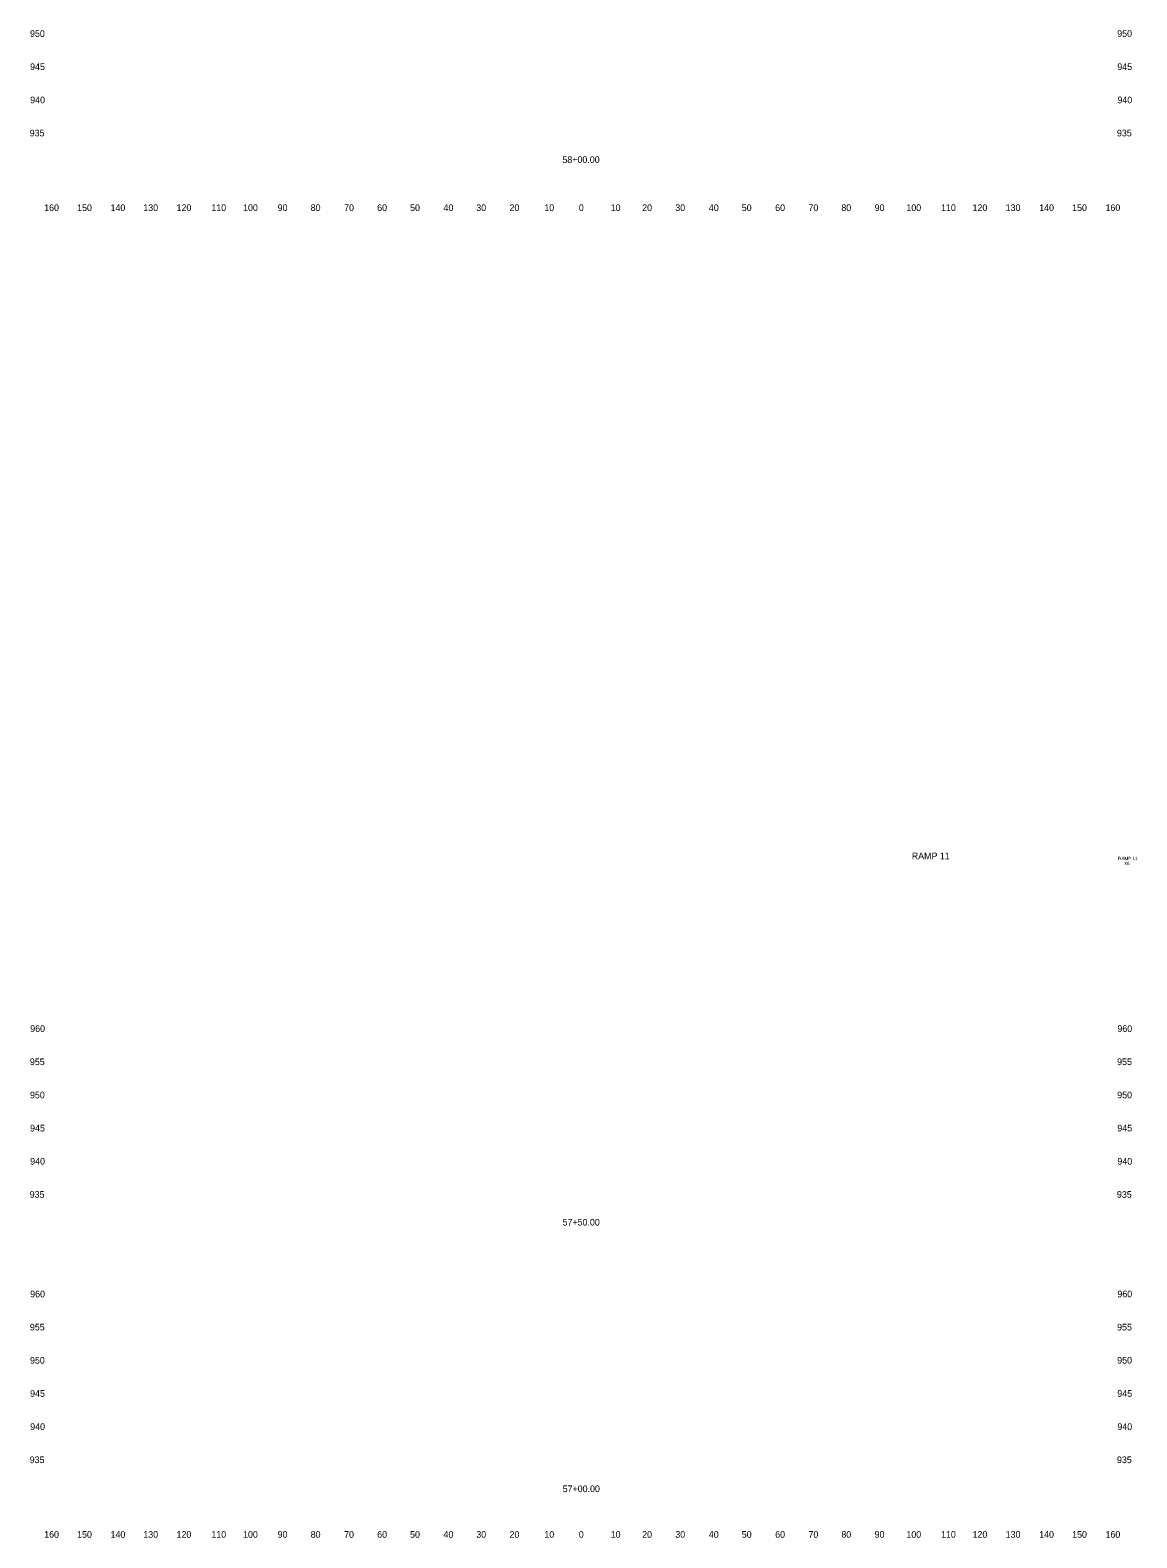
# Model space of a CAD drawing. Extents: x 4994 to 5843, y 4997 to 8804.
# Drawn here: x 4993.9 to 5327.6, y 6997.5 to 7452 of the extents above; entities that cross this region are included whole.
import ezdxf

# ---------------------------------------------------------------- set-up
doc = ezdxf.new("R2010")
doc.units = 0
for name, color, linetype in [('RD_SHT_ID', 7, 'Continuous'), ('RD_XS_TX_Offset', 7, 'Continuous'), ('RD_XS_TX_Station', 7, 'Continuous')]:
    doc.layers.add(name, color=color, linetype=linetype)

msp = doc.modelspace()

# ---------------------------------------------------------------- texts
at = {"layer": 'RD_SHT_ID'}
for s, height, p in [('RAMP 11', 2, (5259.69, 7202.06)), ('RAMP 11', 1, (5321.89, 7201.8)), ('X6', 1, (5323.71, 7200.3))]:
    msp.add_text(s, height=height, dxfattribs=at).set_placement(p)
at = {"layer": 'RD_XS_TX_Offset'}
for s, p in [('950', (4993.83, 7450)), ('950', (5321.63, 7450)), ('945', (4993.86, 7440)), ('945', (5321.66, 7440)), ('940', (4993.89, 7430)), ('940', (5321.69, 7430)), ('935', (4993.75, 7420)), ('935', (5321.55, 7420)), ('160', (4998.1, 7397.5)), ('150', (5008.04, 7397.5)), ('140', (5018.1, 7397.5)), ('130', (5027.99, 7397.5)), ('120', (5038.01, 7397.5)), ('110', (5048.51, 7397.5)), ('100', (5058.07, 7397.5)), ('90', (5068.5, 7397.5)), ('80', (5078.46, 7397.5)), ('70', (5088.54, 7397.5)), ('60', (5098.5, 7397.5)), ('50', (5108.43, 7397.5)), ('40', (5118.5, 7397.5)), ('30', (5128.39, 7397.5)), ('20', (5138.4, 7397.5)), ('10', (5148.91, 7397.5)), ('0', (5159.3, 7397.5)), ('0', (5159.3, 7397.5)), ('10', (5168.91, 7397.5)), ('20', (5178.4, 7397.5)), ('30', (5188.39, 7397.5)), ('40', (5198.5, 7397.5)), ('50', (5208.43, 7397.5)), ('60', (5218.5, 7397.5)), ('70', (5228.54, 7397.5)), ('80', (5238.46, 7397.5)), ('90', (5248.5, 7397.5)), ('100', (5258.07, 7397.5)), ('110', (5268.51, 7397.5)), ('120', (5278.01, 7397.5)), ('130', (5287.99, 7397.5)), ('140', (5298.1, 7397.5)), ('150', (5308.04, 7397.5)), ('160', (5318.1, 7397.5)), ('960', (4993.89, 7150)), ('960', (5321.69, 7150)), ('955', (4993.8, 7140)), ('955', (5321.6, 7140)), ('950', (4993.83, 7130)), ('950', (5321.63, 7130)), ('945', (4993.86, 7120)), ('945', (5321.66, 7120)), ('940', (4993.89, 7110)), ('940', (5321.69, 7110)), ('935', (4993.75, 7100)), ('935', (5321.55, 7100)), ('960', (4993.89, 7070)), ('960', (5321.69, 7070)), ('955', (4993.8, 7060)), ('955', (5321.6, 7060)), ('950', (4993.83, 7050)), ('950', (5321.63, 7050)), ('945', (4993.86, 7040)), ('945', (5321.66, 7040)), ('940', (4993.89, 7030)), ('940', (5321.69, 7030)), ('935', (4993.75, 7020)), ('935', (5321.55, 7020)), ('160', (4998.1, 6997.5)), ('150', (5008.04, 6997.5)), ('140', (5018.1, 6997.5)), ('130', (5027.99, 6997.5)), ('120', (5038.01, 6997.5)), ('110', (5048.51, 6997.5)), ('100', (5058.07, 6997.5)), ('90', (5068.5, 6997.5)), ('80', (5078.46, 6997.5)), ('70', (5088.54, 6997.5)), ('60', (5098.5, 6997.5)), ('50', (5108.43, 6997.5)), ('40', (5118.5, 6997.5)), ('30', (5128.39, 6997.5)), ('20', (5138.4, 6997.5)), ('10', (5148.91, 6997.5)), ('0', (5159.3, 6997.5)), ('0', (5159.3, 6997.5)), ('10', (5168.91, 6997.5)), ('20', (5178.4, 6997.5)), ('30', (5188.39, 6997.5)), ('40', (5198.5, 6997.5)), ('50', (5208.43, 6997.5)), ('60', (5218.5, 6997.5)), ('70', (5228.54, 6997.5)), ('80', (5238.46, 6997.5)), ('90', (5248.5, 6997.5)), ('100', (5258.07, 6997.5)), ('110', (5268.51, 6997.5)), ('120', (5278.01, 6997.5)), ('130', (5287.99, 6997.5)), ('140', (5298.1, 6997.5)), ('150', (5308.04, 6997.5)), ('160', (5318.1, 6997.5))]:
    msp.add_text(s, height=2, dxfattribs=at).set_placement(p)
at = {"layer": 'RD_XS_TX_Station'}
for s, p in [('58+00.00', (5154.35, 7411.99)), ('57+50.00', (5154.4, 7091.63)), ('57+00.00', (5154.43, 7011.26))]:
    msp.add_text(s, height=2, dxfattribs=at).set_placement(p)

doc.saveas('drawing.dxf')
